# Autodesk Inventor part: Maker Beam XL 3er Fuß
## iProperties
Created: 2017-03
Part Number: Maker Beam XL 3er Fuß
Material: Standard
Document SubType Name: Blech
Designer: Acer
Density: 1 g/cm^3
Sheet Metal Rule: Standard_mm
Author: Acer
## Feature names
1. Extrusion3
2. Extrusion5
3. Extrusion6
4. Extrusion7
5. Extrusion8
6. Rundung2 [Fillet]
7. Fase1 [Chamfer]
